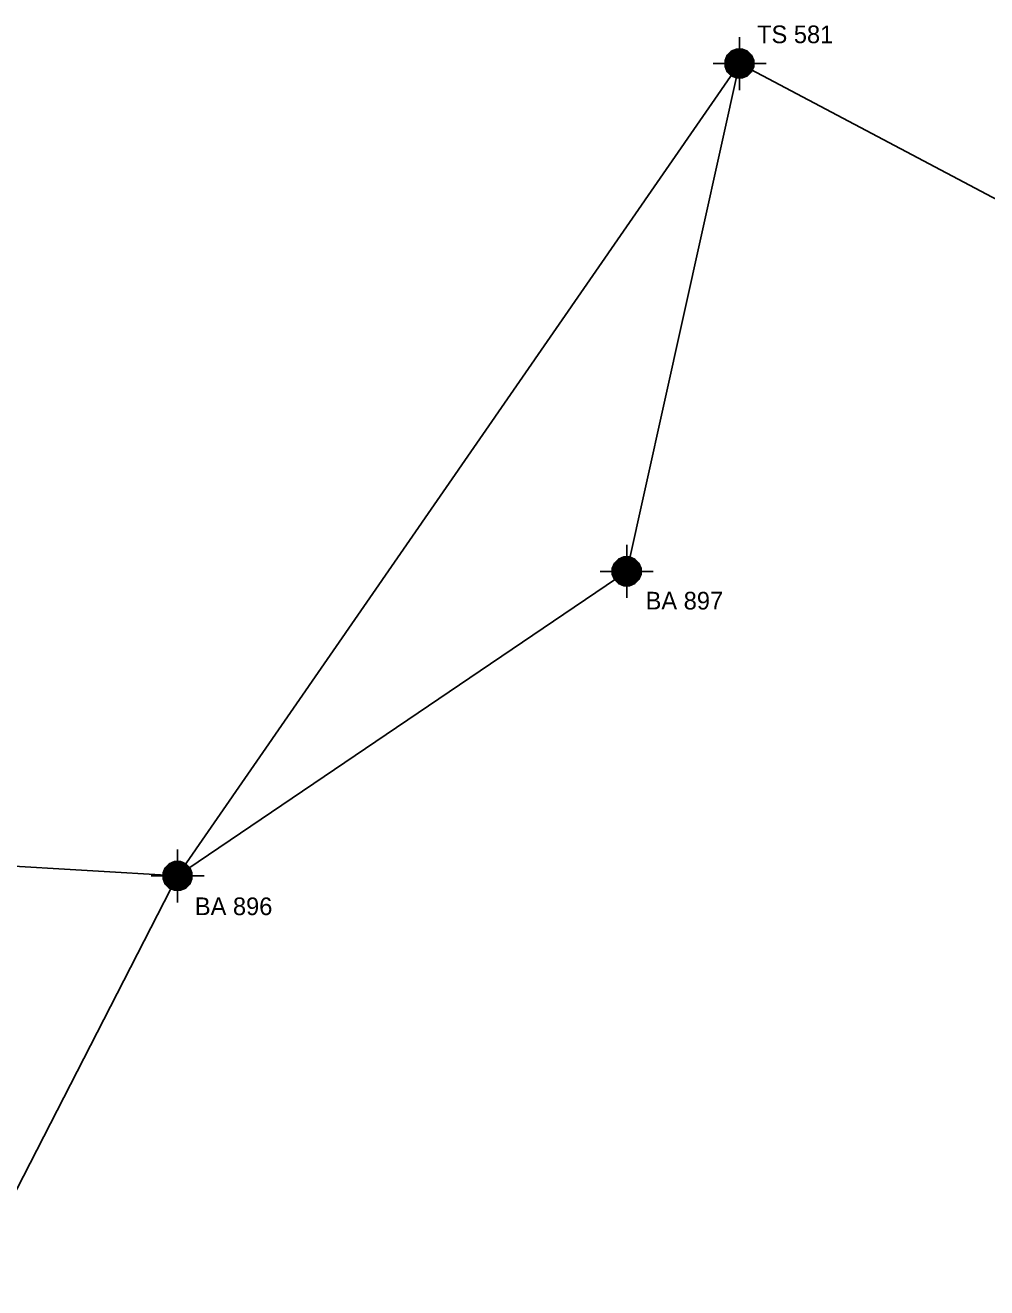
# Model space of a CAD drawing. Extents: x -346533 to -339969, y -1273090 to -1271585.
# Drawn here: x -346053 to -345645, y -1273036 to -1272500 of the extents above; entities that cross this region are included whole.
import ezdxf

# ---------------------------------------------------------------- set-up
doc = ezdxf.new("R2010")
doc.units = 0
for name, color, linetype in [('BP_11', 7, 'Continuous'), ('BP_12', 7, 'Continuous'), ('BP_14', 7, 'Continuous')]:
    doc.layers.add(name, color=color, linetype=linetype)

msp = doc.modelspace()

# ---------------------------------------------------------------- linework, layer by layer
at = {"layer": 'BP_11'}
for points in [[(-345749.57, -1272527.26), (-345749.57, -1272520.91), (-345749.57, -1272514.56), (-345749.57, -1272508.21), (-345749.57, -1272504.76)], [(-345749.57, -1272509.86), (-345748.37, -1272509.86), (-345746.12, -1272510.81), (-345744.42, -1272512.51), (-345743.47, -1272514.76), (-345743.47, -1272517.21), (-345744.42, -1272519.46), (-345746.12, -1272521.16), (-345748.37, -1272522.11), (-345750.82, -1272522.11), (-345753.07, -1272521.16), (-345754.77, -1272519.46), (-345755.72, -1272517.21), (-345755.72, -1272514.76), (-345754.77, -1272512.51), (-345753.07, -1272510.81), (-345750.82, -1272509.86), (-345749.62, -1272509.86), (-345747.82, -1272510.21), (-345751.42, -1272510.21), (-345752.22, -1272510.61), (-345747.02, -1272510.61), (-345746.22, -1272511.01), (-345752.57, -1272511.01), (-345753.02, -1272511.01), (-345753.42, -1272511.41), (-345747.07, -1272511.41), (-345745.82, -1272511.41), (-345745.42, -1272511.81), (-345751.77, -1272511.81), (-345753.82, -1272511.81), (-345754.22, -1272512.21), (-345747.87, -1272512.21), (-345745.02, -1272512.21), (-345744.62, -1272512.61), (-345750.97, -1272512.61), (-345754.62, -1272512.61), (-345754.62, -1272513.01), (-345748.27, -1272513.01), (-345744.62, -1272513.01), (-345744.22, -1272513.41), (-345750.57, -1272513.41), (-345755.02, -1272513.41), (-345755.02, -1272513.81), (-345748.67, -1272513.81), (-345744.22, -1272513.81), (-345743.82, -1272514.21), (-345750.17, -1272514.21), (-345755.42, -1272514.21), (-345755.42, -1272514.61), (-345749.07, -1272514.61), (-345743.82, -1272514.61), (-345743.82, -1272515.01), (-345750.17, -1272515.01), (-345755.42, -1272515.01), (-345755.42, -1272515.41), (-345749.07, -1272515.41), (-345743.82, -1272515.41), (-345743.82, -1272515.81), (-345750.17, -1272515.81), (-345755.42, -1272515.81), (-345755.42, -1272516.21), (-345749.07, -1272516.21), (-345743.82, -1272516.21), (-345743.82, -1272516.61), (-345750.17, -1272516.61), (-345755.42, -1272516.61), (-345755.42, -1272517.01), (-345749.07, -1272517.01), (-345743.82, -1272517.01), (-345743.82, -1272517.41), (-345750.17, -1272517.41), (-345755.42, -1272517.41), (-345755.42, -1272517.81), (-345749.07, -1272517.81), (-345743.82, -1272517.81), (-345744.22, -1272518.21), (-345750.57, -1272518.21), (-345755.02, -1272518.21), (-345755.02, -1272518.61), (-345748.67, -1272518.61), (-345744.22, -1272518.61), (-345744.62, -1272519.01), (-345750.97, -1272519.01), (-345754.62, -1272519.01), (-345754.62, -1272519.41), (-345748.27, -1272519.41), (-345744.62, -1272519.41), (-345745.02, -1272519.81), (-345751.37, -1272519.81), (-345754.22, -1272519.81), (-345753.82, -1272520.21), (-345747.47, -1272520.21), (-345745.42, -1272520.21), (-345745.82, -1272520.61), (-345752.17, -1272520.61), (-345753.42, -1272520.61), (-345753.02, -1272521.01), (-345746.67, -1272521.01), (-345746.22, -1272521.01)], [(-345760.82, -1272516.01), (-345754.47, -1272516.01), (-345748.12, -1272516.01), (-345741.77, -1272516.01), (-345738.32, -1272516.01)], [(-345746.22, -1272521.01), (-345747.02, -1272521.41), (-345752.22, -1272521.41), (-345751.42, -1272521.81), (-345747.82, -1272521.81)], [(-345797.49, -1272742.99), (-345797.49, -1272736.64), (-345797.49, -1272730.29), (-345797.49, -1272723.94), (-345797.49, -1272720.49)], [(-345797.49, -1272725.59), (-345796.29, -1272725.59), (-345794.04, -1272726.54), (-345792.34, -1272728.24), (-345791.39, -1272730.49), (-345791.39, -1272732.94), (-345792.34, -1272735.19), (-345794.04, -1272736.89), (-345796.29, -1272737.84), (-345798.74, -1272737.84), (-345800.99, -1272736.89), (-345802.69, -1272735.19), (-345803.64, -1272732.94), (-345803.64, -1272730.49), (-345802.69, -1272728.24), (-345800.99, -1272726.54), (-345798.74, -1272725.59), (-345797.54, -1272725.59), (-345795.74, -1272725.94), (-345799.34, -1272725.94), (-345800.14, -1272726.34), (-345794.94, -1272726.34), (-345794.14, -1272726.74), (-345800.49, -1272726.74), (-345800.94, -1272726.74), (-345801.34, -1272727.14), (-345794.99, -1272727.14), (-345793.74, -1272727.14), (-345793.34, -1272727.54), (-345799.69, -1272727.54), (-345801.74, -1272727.54), (-345802.14, -1272727.94), (-345795.79, -1272727.94), (-345792.94, -1272727.94), (-345792.54, -1272728.34), (-345798.89, -1272728.34), (-345802.54, -1272728.34), (-345802.54, -1272728.74), (-345796.19, -1272728.74), (-345792.54, -1272728.74), (-345792.14, -1272729.14), (-345798.49, -1272729.14), (-345802.94, -1272729.14), (-345802.94, -1272729.54), (-345796.59, -1272729.54), (-345792.14, -1272729.54), (-345791.74, -1272729.94), (-345798.09, -1272729.94), (-345803.34, -1272729.94), (-345803.34, -1272730.34), (-345796.99, -1272730.34), (-345791.74, -1272730.34), (-345791.74, -1272730.74), (-345798.09, -1272730.74), (-345803.34, -1272730.74), (-345803.34, -1272731.14), (-345796.99, -1272731.14), (-345791.74, -1272731.14), (-345791.74, -1272731.54), (-345798.09, -1272731.54), (-345803.34, -1272731.54), (-345803.34, -1272731.94), (-345796.99, -1272731.94), (-345791.74, -1272731.94), (-345791.74, -1272732.34), (-345798.09, -1272732.34), (-345803.34, -1272732.34), (-345803.34, -1272732.74), (-345796.99, -1272732.74), (-345791.74, -1272732.74), (-345791.74, -1272733.14), (-345798.09, -1272733.14), (-345803.34, -1272733.14), (-345803.34, -1272733.54), (-345796.99, -1272733.54), (-345791.74, -1272733.54), (-345792.14, -1272733.94), (-345798.49, -1272733.94), (-345802.94, -1272733.94), (-345802.94, -1272734.34), (-345796.59, -1272734.34), (-345792.14, -1272734.34), (-345792.54, -1272734.74), (-345798.89, -1272734.74), (-345802.54, -1272734.74), (-345802.54, -1272735.14), (-345796.19, -1272735.14), (-345792.54, -1272735.14), (-345792.94, -1272735.54), (-345799.29, -1272735.54), (-345802.14, -1272735.54), (-345801.74, -1272735.94), (-345795.39, -1272735.94), (-345793.34, -1272735.94), (-345793.74, -1272736.34), (-345800.09, -1272736.34), (-345801.34, -1272736.34), (-345800.94, -1272736.74), (-345794.59, -1272736.74), (-345794.14, -1272736.74)], [(-345808.74, -1272731.74), (-345802.39, -1272731.74), (-345796.04, -1272731.74), (-345789.69, -1272731.74), (-345786.24, -1272731.74)], [(-345794.14, -1272736.74), (-345794.94, -1272737.14), (-345800.14, -1272737.14), (-345799.34, -1272737.54), (-345795.74, -1272737.54)], [(-345988.21, -1272872.37), (-345988.21, -1272866.02), (-345988.21, -1272859.67), (-345988.21, -1272853.32), (-345988.21, -1272849.87)], [(-345988.21, -1272854.97), (-345987.01, -1272854.97), (-345984.76, -1272855.92), (-345983.06, -1272857.62), (-345982.11, -1272859.87), (-345982.11, -1272862.32), (-345983.06, -1272864.57), (-345984.76, -1272866.27), (-345987.01, -1272867.22), (-345989.46, -1272867.22), (-345991.71, -1272866.27), (-345993.41, -1272864.57), (-345994.36, -1272862.32), (-345994.36, -1272859.87), (-345993.41, -1272857.62), (-345991.71, -1272855.92), (-345989.46, -1272854.97), (-345988.26, -1272854.97), (-345986.46, -1272855.32), (-345990.06, -1272855.32), (-345990.86, -1272855.72), (-345985.66, -1272855.72), (-345984.86, -1272856.12), (-345991.21, -1272856.12), (-345991.66, -1272856.12), (-345992.06, -1272856.52), (-345985.71, -1272856.52), (-345984.46, -1272856.52), (-345984.06, -1272856.92), (-345990.41, -1272856.92), (-345992.46, -1272856.92), (-345992.86, -1272857.32), (-345986.51, -1272857.32), (-345983.66, -1272857.32), (-345983.26, -1272857.72), (-345989.61, -1272857.72), (-345993.26, -1272857.72), (-345993.26, -1272858.12), (-345986.91, -1272858.12), (-345983.26, -1272858.12), (-345982.86, -1272858.52), (-345989.21, -1272858.52), (-345993.66, -1272858.52), (-345993.66, -1272858.92), (-345987.31, -1272858.92), (-345982.86, -1272858.92), (-345982.46, -1272859.32), (-345988.81, -1272859.32), (-345994.06, -1272859.32), (-345994.06, -1272859.72), (-345987.71, -1272859.72), (-345982.46, -1272859.72), (-345982.46, -1272860.12), (-345988.81, -1272860.12), (-345994.06, -1272860.12), (-345994.06, -1272860.52), (-345987.71, -1272860.52), (-345982.46, -1272860.52), (-345982.46, -1272860.92), (-345988.81, -1272860.92), (-345994.06, -1272860.92), (-345994.06, -1272861.32), (-345987.71, -1272861.32), (-345982.46, -1272861.32), (-345982.46, -1272861.72), (-345988.81, -1272861.72), (-345994.06, -1272861.72), (-345994.06, -1272862.12), (-345987.71, -1272862.12), (-345982.46, -1272862.12), (-345982.46, -1272862.52), (-345988.81, -1272862.52), (-345994.06, -1272862.52), (-345994.06, -1272862.92), (-345987.71, -1272862.92), (-345982.46, -1272862.92), (-345982.86, -1272863.32), (-345989.21, -1272863.32), (-345993.66, -1272863.32), (-345993.66, -1272863.72), (-345987.31, -1272863.72), (-345982.86, -1272863.72), (-345983.26, -1272864.12), (-345989.61, -1272864.12), (-345993.26, -1272864.12), (-345993.26, -1272864.52), (-345986.91, -1272864.52), (-345983.26, -1272864.52), (-345983.66, -1272864.92), (-345990.01, -1272864.92), (-345992.86, -1272864.92), (-345992.46, -1272865.32), (-345986.11, -1272865.32), (-345984.06, -1272865.32), (-345984.46, -1272865.72), (-345990.81, -1272865.72), (-345992.06, -1272865.72), (-345991.66, -1272866.12), (-345985.31, -1272866.12), (-345984.86, -1272866.12)], [(-345999.46, -1272861.12), (-345993.11, -1272861.12), (-345986.76, -1272861.12), (-345980.41, -1272861.12), (-345976.96, -1272861.12)], [(-345984.86, -1272866.12), (-345985.66, -1272866.52), (-345990.86, -1272866.52), (-345990.06, -1272866.92), (-345986.46, -1272866.92)]]:
    msp.add_lwpolyline(points, dxfattribs=at)
for points in [[(-345748.37, -1272509.86), (-345746.12, -1272510.81), (-345744.42, -1272512.51), (-345743.47, -1272514.76), (-345743.47, -1272517.21), (-345744.42, -1272519.46), (-345746.12, -1272521.16), (-345748.37, -1272522.11), (-345750.82, -1272522.11), (-345753.07, -1272521.16), (-345754.77, -1272519.46), (-345755.72, -1272517.21), (-345755.72, -1272514.76), (-345754.77, -1272512.51), (-345753.07, -1272510.81), (-345750.82, -1272509.86)], [(-345796.29, -1272725.59), (-345794.04, -1272726.54), (-345792.34, -1272728.24), (-345791.39, -1272730.49), (-345791.39, -1272732.94), (-345792.34, -1272735.19), (-345794.04, -1272736.89), (-345796.29, -1272737.84), (-345798.74, -1272737.84), (-345800.99, -1272736.89), (-345802.69, -1272735.19), (-345803.64, -1272732.94), (-345803.64, -1272730.49), (-345802.69, -1272728.24), (-345800.99, -1272726.54), (-345798.74, -1272725.59)], [(-345987.01, -1272854.97), (-345984.76, -1272855.92), (-345983.06, -1272857.62), (-345982.11, -1272859.87), (-345982.11, -1272862.32), (-345983.06, -1272864.57), (-345984.76, -1272866.27), (-345987.01, -1272867.22), (-345989.46, -1272867.22), (-345991.71, -1272866.27), (-345993.41, -1272864.57), (-345994.36, -1272862.32), (-345994.36, -1272859.87), (-345993.41, -1272857.62), (-345991.71, -1272855.92), (-345989.46, -1272854.97)]]:
    msp.add_lwpolyline(points, close=True, dxfattribs=at)
at = {"layer": 'BP_14'}
for p, q in [((-345988.21, -1272861.12), (-345749.57, -1272516.01)), ((-345749.57, -1272516.01), (-345797.49, -1272731.74)), ((-345749.57, -1272516.01), (-345551.44, -1272620.96)), ((-345797.49, -1272731.74), (-345988.21, -1272861.12)), ((-345988.21, -1272861.12), (-346180.05, -1272849.62)), ((-346078.01, -1273036.07), (-345988.21, -1272861.12))]:
    msp.add_line(p, q, dxfattribs=at)

# ---------------------------------------------------------------- texts
at = {"layer": 'BP_12'}
for s, p in [('TS 581', (-345742.11, -1272507.35)), ('BA 897', (-345789.45, -1272747.93)), ('BA 896', (-345980.85, -1272877.77))]:
    msp.add_text(s, height=7.5, dxfattribs=at).set_placement(p)

doc.saveas('drawing.dxf')
